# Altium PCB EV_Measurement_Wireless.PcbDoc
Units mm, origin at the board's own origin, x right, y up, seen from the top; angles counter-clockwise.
Board outline 60 x 45 mm, 4 copper layers (Top Layer, Mid-Layer 1, Mid_Layer 2, Bottom Layer), stack 0.605 mm thick; 30 components, 26 nets, 281 pads, 0 vias.
Unrouted connection lines stored in the file: 178.
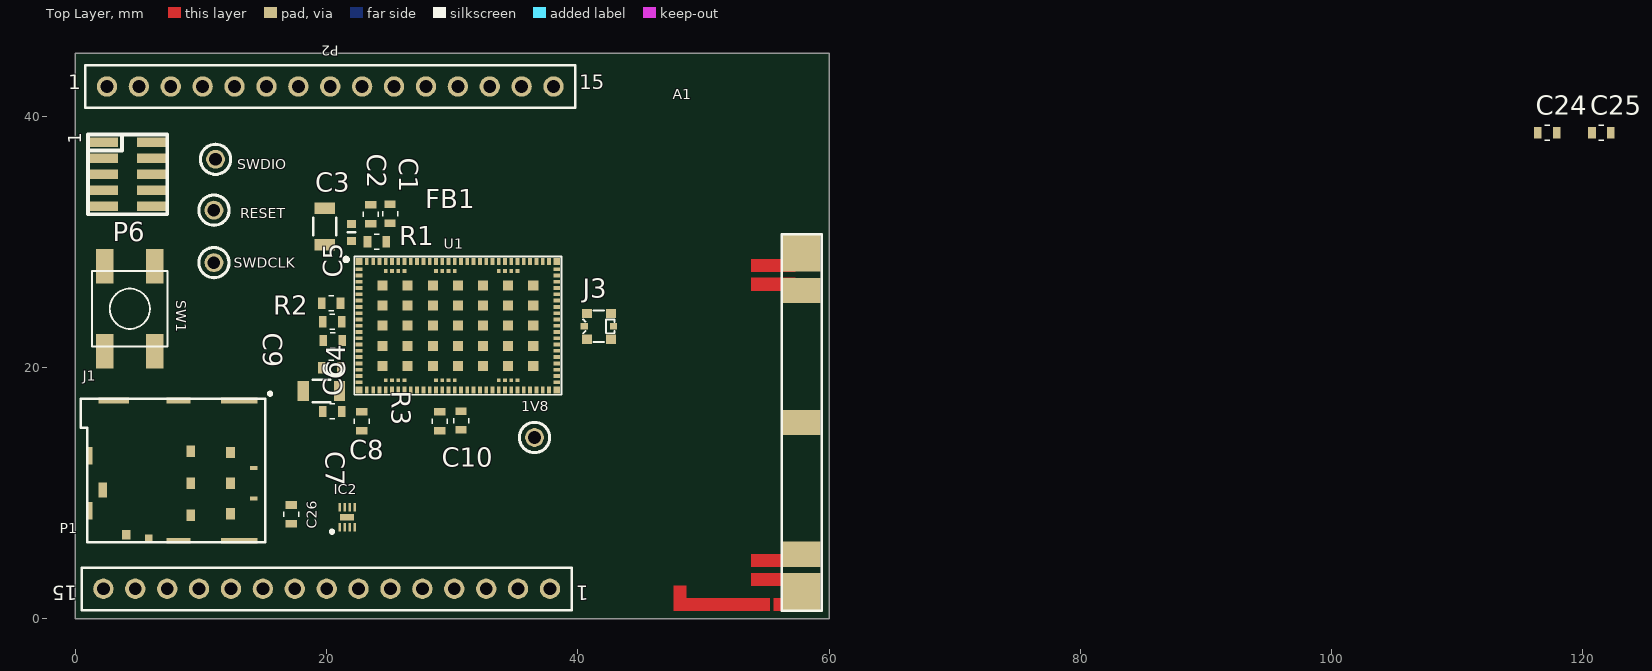
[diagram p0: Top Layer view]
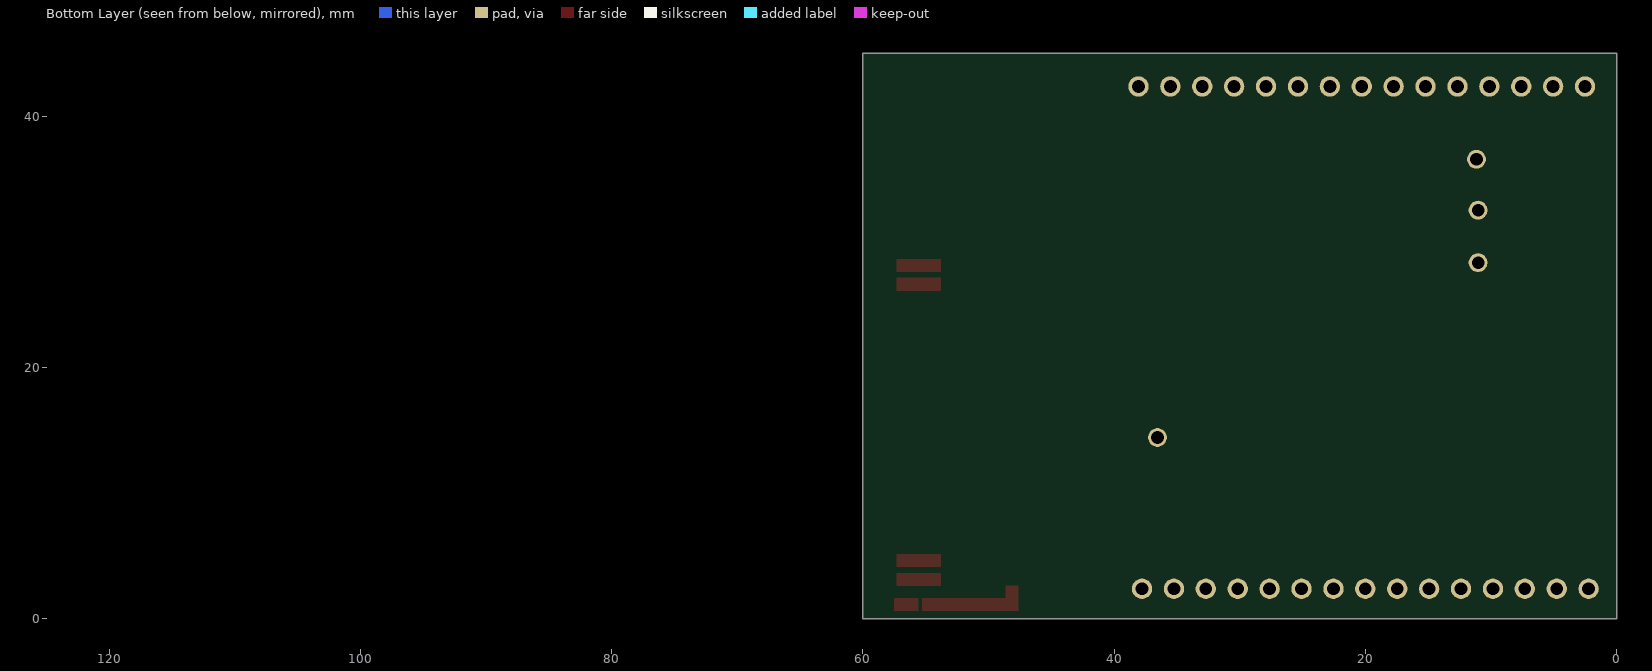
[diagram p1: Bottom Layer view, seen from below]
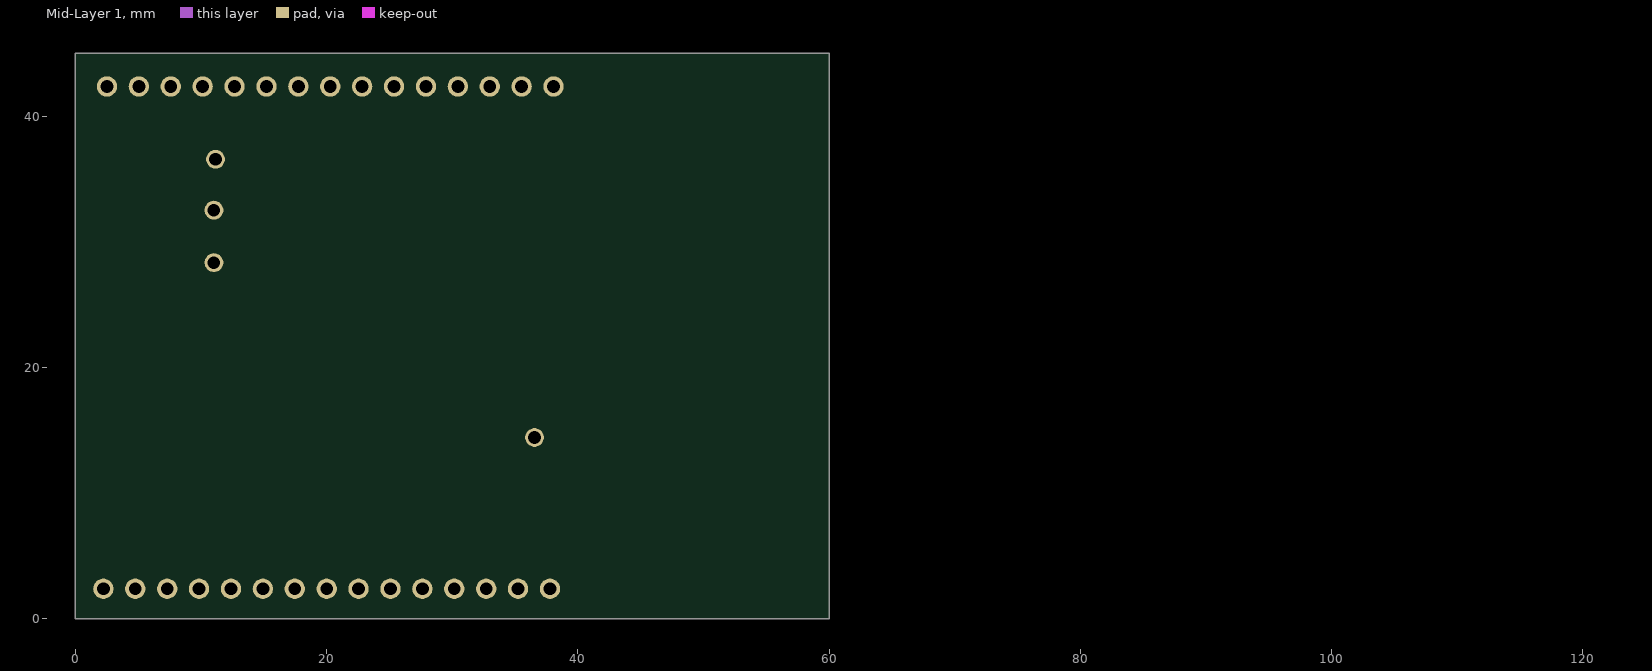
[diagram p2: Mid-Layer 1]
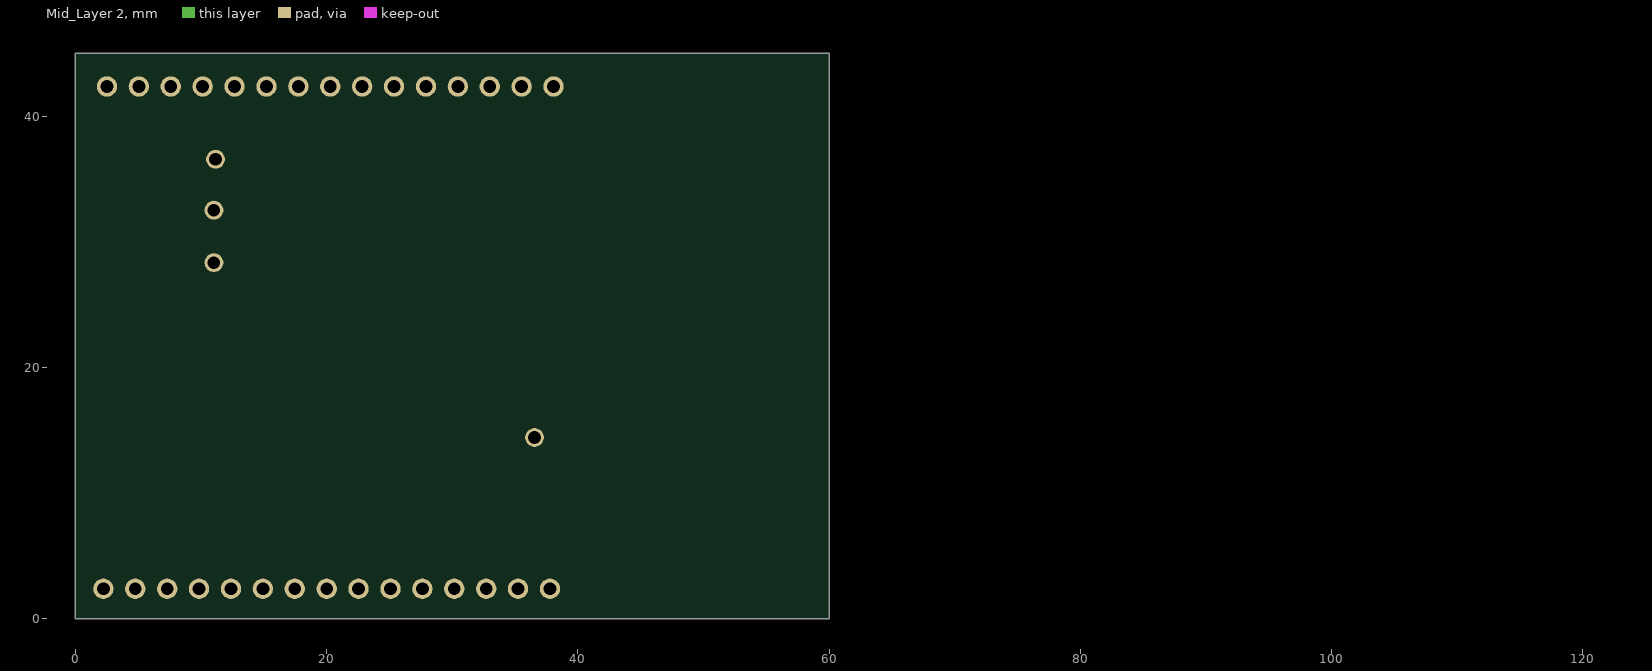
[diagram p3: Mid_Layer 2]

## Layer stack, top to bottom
Top Solder: solder mask 0.0102, Solder Resist, Dk 3.5
Top Layer: signal copper 0.0356
Dielectric 2: prepreg 0.0711, PP-006, Dk 4.1
Mid-Layer 1: signal copper 0.0356
Dielectric 1: prepreg 0.0711, PP-006, Dk 4.1
Mid_Layer 2: signal copper 0.0356
Dielectric2: dielectric 0.32, FR-4, Dk 4.1
Bottom Layer: signal copper 0.0356
Bottom Solder: solder mask 0.0102, Solder Resist, Dk 3.5

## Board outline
0,0 0,45 60,45 60,0

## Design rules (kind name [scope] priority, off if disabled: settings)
Clearance [All] p1: gap=0.254 ignorepadtopadclearanceinfootprint=FALSE
PolygonConnect [All] p1: connectstyle=Relief reliefconductorwidth=0.254 reliefentries=4 polygonreliefangle="90 Angle" airgapwidth=0.254
RoutingVias [All] p1: holewidth=0.711 width=1.27 viastyle="Through Hole" minholewidth=0.711 minwidth=1.27 maxholewidth=0.711 maxwidth=1.27
SolderMaskExpansion [All] p1: expansion=0.102 istentingtop=FALSE
SupplyNets "Schematic Supply Nets" [InNet('VDD_GPIO')] p1: voltage=0.000
SupplyNets "Schematic Supply Nets_1" [InNet('GND')] p2: voltage=0.000
Width [All] p1: maxlimit=0.254 minlimit=0.254 preferedwidth=0.254
30 further rules are at their usual default settings.

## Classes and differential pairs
component class sheet4_sim_connections: 1V8 C24 C25 C26 IC2 J1 P1 P2 P6 RESET SWDCLK SWDIO
component class sheet2_nRF9160: A1 C1 C2 C3 C4 C5 C6 C7 C8 C9 C10 FB1 J3 R1 R2 R3 SW1 U1

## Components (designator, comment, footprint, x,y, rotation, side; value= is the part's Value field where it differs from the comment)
1V8 "TESTPOINT_Black_Small" Testpoint_Black_Small 36.55,14.425 r0 top
A1 "FR01-S4-210" FR01-S4-210_DF 57.825,15.625 r270 top
C1 "39p" 0603(1608)C 25.05,32.25 r90 top
C2 "100n" 0603(1608)C 23.5,32.2 r90 top
C3 "47u" 1206(3216)C 19.85,31.225 r270 top
C4 "100n" 0603(1608)C 20.45,23.65 r180 top
C5 "4u7" 0603(1608)C 20.35,25.125 r180 top
C6 "4u7" 0603(1608)C 20.475,22.15 r180 top
C7 "15p" 0603(1608)C 20.45,16.5 r180 top value=39p
C8 "100n" 0603(1608)C 22.8,15.725 r270 top
C9 "47u" 1206(3216)C 19.575,18.125 r180 top
C10 "100n" 0603(1608)C 30.7,15.775 r90 top
C24 "100n" 0603(1608)C 117.184,38.692 r0 top
C25 "100n" 0603(1608)C 121.502,38.692 r0 top
C26 "100n" 0603(1608)C 17.175,8.3 r270 top
FB1 "BLM18EG221SN1D" BLM18SP221SN1B 21.975,30.75 r270 top
IC2 "EMIF03SIM02M8" SON40P150X170X60-9N-D 21.625,8.075 r90 top
J1 "SF72S006VBAR2500" SF72S006VBAR2500 14.945,17.365 r90 top
J3 "MM8130-2600" COAXIAL-SWF 41.675,23.275 r90 top
P1 "SAMTEC-HTSW-115-17-X-SJ" SAMTEC-HTSW-115-17-X-S 20,2.375 r180 top
P2 "SAMTEC-HTSW-115-17-X-SJ" SAMTEC-HTSW-115-17-X-S 20.285,42.375 r0 top
P6 "Pin Header 2x5, 1.27mm" HDR_2x5-SMD-1.27mm-K 4.15,35.375 r270 top
R1 "10k" 0603(1608) 24,30 r0 top
R2 "0" 0603(1608) 20.375,19.975 r0 top value=0E
R3 "1k" 0603(1608) 29,15.725 r270 top
RESET "TESTPOINT_Black_Small" Testpoint_Black_Small 11.025,32.525 r0 top
SW1 "PB SW" Switch-PB-6.2x6.3mm-SMD 4.325,24.675 r90 top
SWDCLK "TESTPOINT_Black_Small" Testpoint_Black_Small 11.025,28.35 r90 top
SWDIO "TESTPOINT_Black_Small" Testpoint_Black_Small 11.15,36.575 r90 top
U1 "nRF9160-SICAB1A" LGA50P1600X1050X104-161N 30.45,23.325 r0 top

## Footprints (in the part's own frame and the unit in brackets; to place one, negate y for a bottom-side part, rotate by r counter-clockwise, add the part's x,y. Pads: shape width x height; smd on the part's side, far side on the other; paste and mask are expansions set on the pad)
0603(1608) [mm] "Chip 0603 (1608 metric)"
  rect 0.6x0.9 smd: 1(-0.75,0) 2(0.75,0)
  silkscreen extent -0.2,-0.6 0.2,0.6, body extent -0.8,-0.4 0.8,0.4, height 0.3
0603(1608)C [mm] "Chip 0603 (1608 metric)"
  rect 0.6x0.9 smd: 1(-0.75,0) 2(0.75,0)
  silkscreen extent -0.2,-0.6 0.2,0.6, body extent -0.8,-0.38 0.8,0.42, height 0.5
1206(3216)C [mm] "Chip Capa 1206 (3216 metric)"
  rect 0.9x1.6 smd: 1(-1.45,0) 2(1.45,0)
  silkscreen extent -0.7,-0.9 0.7,0.9, body extent -1.6,-0.8 1.6,0.8, height 1
BLM18SP221SN1B [mm]
  rect 0.65x0.7 smd: 1(-0.675,0) 2(0.675,0)
  silkscreen extent 0,-0.3 0,0.3, body extent -0.8,-0.4 0.8,0.4, height 0.8
COAXIAL-SWF [mm]
  rect 0.5x0.58 smd: 1(0,1.16) 3(0,-1.16)
  rect 0.75x0.8 smd: 2(-1.025,-0.95) 2(-1.025,0.95) 2(1.025,-0.95) 2(1.025,0.95)
  Top Layer pour cut-out: -0.65,0.55 0.65,0.55 0.65,1.35 -0.65,1.35
  Top Layer pour cut-out: 0.65,-0.55 -0.65,-0.55 -0.65,-1.35 0.65,-1.35
  silkscreen extent -1.25,-1.25 1.25,1.25, body extent -1.26,-1.3 1.26,1.3, height 1.55
FR01-S4-210_DF [mm]
  rect 2x3 smd: 0(0,0) 2(10.5,0) 4(-10.5,0)
  rect 3x3 smd: 1(13.5,0) 3(-13.5,0)
  Top Layer region: 15,-2.243 15,-0.312 14,-0.312 14,-2.243
  Top Layer region: 14,-2.547 15,-2.547 15,-10.022 14,-10.022
  Top Layer region: 13,-0.5 12,-0.5 12,-4 13,-4
  Top Layer region: 11.5,-0.5 10.5,-0.5 10.5,-4 11.5,-4
  Top Layer region: -12,-0.5 -13,-0.5 -13,-4 -12,-4
  Top Layer region: -10.5,-0.5 -11.5,-0.5 -11.5,-4 -10.5,-4
  Top Layer pour cut-out: -25,2 15.4,2 15.4,-10.5 -25,-10.5
  Top Layer region: 15,-9.2 15,-10.2 13,-10.2 13,-9.2
  Mid-Layer 1 pour cut-out: -25,2 15.4,2 15.4,-10.5 -25,-10.5
  Mid_Layer 2 pour cut-out: -25,2 15.4,2 15.4,-10.5 -25,-10.5
  Bottom Layer pour cut-out: -25,2 15.4,2 15.4,-10.5 -25,-10.5
  silkscreen extent -15,-1.6 15,1.6, body extent -15,-1.5 15,1.5, height 1
HDR_2x5-SMD-1.27mm-K [mm]
  rect 0.76x2.4 smd: 1(-2.54,-1.95) 2(-2.54,1.95) 3(-1.27,-1.95) 4(-1.27,1.95) 5(0,-1.95) 6(0,1.95) 7(1.27,-1.95) 8(1.27,1.95) 9(2.54,-1.95) 10(2.54,1.95)
  silkscreen extent -3.18,-3.15 3.18,3.15, body extent -3.14,-2.92 3.14,2.92, height 6.11
LGA50P1600X1050X104-161N [mm]
  rect 0.54x0.54 smd mask+0.05: 1(-7.87,5.12) 21(-7.87,-5.12) 52(7.87,-5.12) 72(7.87,5.12)
  rect 0.54x0.3 smd mask+0.05: 2(-7.87,4.5) 3(-7.87,4) 4(-7.87,3.5) 5(-7.87,3) 6(-7.87,2.5) 7(-7.87,2) 8(-7.87,1.5) 9(-7.87,1) 10(-7.87,0.5) 11(-7.87,0) 12(-7.87,-0.5) 13(-7.87,-1) 14(-7.87,-1.5) 15(-7.87,-2) 16(-7.87,-2.5) 17(-7.87,-3) 18(-7.87,-3.5) 19(-7.87,-4) 20(-7.87,-4.5) 53(7.87,-4.5) 54(7.87,-4) 55(7.87,-3.5) 56(7.87,-3) 57(7.87,-2.5) 58(7.87,-2) 59(7.87,-1.5) 60(7.87,-1) 61(7.87,-0.5) 62(7.87,0) 63(7.87,0.5) 64(7.87,1) 65(7.87,1.5) 66(7.87,2) 67(7.87,2.5) 68(7.87,3) 69(7.87,3.5) 70(7.87,4) 71(7.87,4.5)
  rect 0.3x0.54 smd mask+0.05: 22(-7.25,-5.12) 23(-6.75,-5.12) 24(-6.25,-5.12) 25(-5.75,-5.12) 26(-5.25,-5.12) 27(-4.75,-5.12) 28(-4.25,-5.12) 29(-3.75,-5.12) 30(-3.25,-5.12) 31(-2.75,-5.12) 32(-2.25,-5.12) 33(-1.75,-5.12) 34(-1.25,-5.12) 35(-0.75,-5.12) 36(-0.25,-5.12) 37(0.25,-5.12) 38(0.75,-5.12) 39(1.25,-5.12) 40(1.75,-5.12) 41(2.25,-5.12) 42(2.75,-5.12) 43(3.25,-5.12) 44(3.75,-5.12) 45(4.25,-5.12) 46(4.75,-5.12) 47(5.25,-5.12) 48(5.75,-5.12) 49(6.25,-5.12) 50(6.75,-5.12) 51(7.25,-5.12) 73(7.25,5.12) 74(6.75,5.12) 75(6.25,5.12) 76(5.75,5.12) 77(5.25,5.12) 78(4.75,5.12) 79(4.25,5.12) 80(3.75,5.12) 81(3.25,5.12) 82(2.75,5.12) 83(2.25,5.12) 84(1.75,5.12) 85(1.25,5.12) 86(0.75,5.12) 87(0.25,5.12) 88(-0.25,5.12) 89(-0.75,5.12) 90(-1.25,5.12) 91(-1.75,5.12) 92(-2.25,5.12) 93(-2.75,5.12) 94(-3.25,5.12) 95(-3.75,5.12) 96(-4.25,5.12) 97(-4.75,5.12) 98(-5.25,5.12) 99(-5.75,5.12) 100(-6.25,5.12) 101(-6.75,5.12) 102(-7.25,5.12)
  rect 0.8x0.8 smd mask+0.05: 103(-6,-3.2) 103(-6,-1.6) 103(-6,0) 103(-6,1.6) 103(-6,3.2) 103(-4,-3.2) 103(-4,-1.6) 103(-4,0) 103(-4,1.6) 103(-4,3.2) 103(-2,-3.2) 103(-2,-1.6) 103(-2,0) 103(-2,1.6) 103(-2,3.2) 103(0,-3.2) 103(0,-1.6) 103(0,0) 103(0,1.6) 103(0,3.2) 103(2,-3.2) 103(2,-1.6) 103(2,0) 103(2,1.6) 103(2,3.2) 103(4,-3.2) 103(4,-1.6) 103(4,0) 103(4,1.6) 103(4,3.2) 103(6,-3.2) 103(6,-1.6) 103(6,0) 103(6,1.6) 103(6,3.2)
  rect 0.3x0.3 smd mask+0.05: 104(-5.75,-4.35) 105(-5.25,-4.35) 106(-4.75,-4.35) 107(-4.25,-4.35) 108(-1.75,-4.35) 109(-1.25,-4.35) 110(-0.75,-4.35) 111(-0.25,-4.35) 112(3.25,-4.35) 113(3.75,-4.35) 114(4.25,-4.35) 115(4.75,-4.35) 116(4.75,4.35) 117(4.25,4.35) 118(3.75,4.35) 119(3.25,4.35) 120(-0.25,4.35) 121(-0.75,4.35) 122(-1.25,4.35) 123(-1.75,4.35) 124(-4.25,4.35) 125(-4.75,4.35) 126(-5.25,4.35) 127(-5.75,4.35)
  Top Layer pour cut-out: -8.15,5.4 8.15,5.4 8.15,-5.4 -8.15,-5.4
  silkscreen extent -9.05,-5.5 8.25,5.5, body extent -8.05,-5.3 8.05,5.3, height 1.2
SAMTEC-HTSW-115-17-X-S [mm]
  round 1.62 hole 1.02: 1(-17.78,0) 2(-15.24,0) 3(-12.7,0) 4(-10.16,0) 5(-7.62,0) 6(-5.08,0) 7(-2.54,0) 8(0,0) 9(2.54,0) 10(5.08,0) 11(7.62,0) 12(10.16,0) 13(12.7,0) 14(15.24,0) 15(17.78,0)
  silkscreen extent -19.5,-1.69 19.5,1.69
SF72S006VBAR2500 [mm]
  rect 0.45x2.9 smd: 0(-11.175,1.9) 0(0,1.9)
  rect 0.45x1.9 smd: 0(-11.175,6.75) 0(0,6.75)
  rect 0.75x0.7 smd: 0(-10.675,10.9)
  rect 1.4x0.5 smd: 0(-8.78,13.85) 0(-4.38,13.85)
  rect 0.3x0.6 smd: 0(-7.8,0.75) 0(-5.36,0.75)
  rect 0.45x2.4 smd: 0(0,11.9)
  rect 0.9x0.7 smd: C1(-4.14,2.6) C2(-6.58,2.6) C3(-9.02,2.6) C5(-4.04,5.77) C6(-6.58,5.77) C7(-9.12,5.77)
  rect 0.6x0.6 smd: CSW(-10.95,9.1)
  rect 1.2x0.65 smd: DSW(-7.13,12.775)
  Top Layer pour cut-out: -10.084,9.5 -3.073,9.5 -3.073,-0.025 -10.084,-0.025
  Top Layer pour cut-out: -8.407,13.106 -3.48,13.106 -3.48,9.855 -8.407,9.855
  silkscreen extent -11.3,-0.67 0.67,14.53, body extent -11.2,0.05 0.02,14.4, height 1.25
SON40P150X170X60-9N-D [mm]
  rect 0.7x0.2 smd: 1(-0.8,0.6) 2(-0.8,0.2) 3(-0.8,-0.2) 4(-0.8,-0.6) 5(0.8,-0.6) 6(0.8,-0.2) 7(0.8,0.2) 8(0.8,0.6)
  rect 0.5x1.1 smd: 9(0,0)
  silkscreen extent -1.27,1.07 -1.03,1.32, body extent -0.8,-0.85 0.8,0.85, height 0.6
Switch-PB-6.2x6.3mm-SMD [mm]
  rect 2.75x1.4 smd: 1(-3.375,2) 1(3.375,2) 2(-3.375,-2) 2(3.375,-2)
  silkscreen extent -3,-3 3,3, body extent -4,-3 4,3.3, height 3.1
Testpoint_Black_Small [mm]
  round 1.5 hole 1: 1(0,0)
  silkscreen extent -1.2,-1.2 1.2,1.2, body extent -1.27,-1.27 1.27,1.27, height 4.89

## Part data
1V8 RESET SWDCLK SWDIO: "PCB Test Point, Black, Through Hole Mount, 3.2 mm, Phosphor Bronze", Manufacturer=MULTICOMP, Manufacturer P/N=TEST-1(R)
A1: library part FR01-S4-210-D, "Mobile IoT LTE Multi-Band Antenna", Manufacturer="Fractus Antennas", Part number IPS=80000001819, Supplier Part Number 1=N.A.
C1 C7: library part C0603_1_39p_50V, "Cer Chip Capacitor / 15p/ +-1%/ 50V", Manufacturer=Murata, Manufacturer P/N=GCM1885C1H390FA16J, Special Value 1=+-1%, Special Value 2=50V
C2 C4 C8 C10 C24 C25 C26: library part C0603_5_100n_25V, "Cer Chip Capacitor / 100n/ +-5%/ 25V", Capacitance=100nF, Case Code (Imperial)=0603, Case Code (Metric)=1608, Dielectric=X7R, Manufacturer 1=Yageo, Manufacturer Part Number=CC0603KRX7R8BB104, Max Operating Temperature=125°C, Min Operating Temperature=-55°C, Package Quantity=1, Special Value 1=+-5%, Special Value 2=25V, Supplier Part Number 1=311-1341-1-ND, Tolerance=10%
C3 C9: library part C1206_7_47u_6.3V, "Cer Chip Capacitor / 47u/ +-10%/ 6.3V", Capacitance=47uF, Case Code (Imperial)=1206, Case Code (Metric)=3216, Dielectric=X5R, Manufacturer 1=Samsung, Manufacturer Part Number=CL31A476MQHNNNE, Max Operating Temperature=85°C, Min Operating Temperature=-55°C, Package Quantity=1, Special Value 1=+-20%, Special Value 2=6.3V, Supplier Part Number 1=1276-1167-1-ND, Tolerance=20%
C5 C6: library part C0603_6_4u7_25V, "Cer Chip Capacitor / 4u7/ +-10%/ 25V", Capacitance=4.7uF, Case Code (Imperial)=0603, Case Code (Metric)=1608, Dielectric=X5R, Manufacturer 1=Samsung, Manufacturer Part Number=CL10A475MA8NQNC, Max Operating Temperature=85°C, Min Operating Temperature=-55°C, Package Quantity=1, Special Value 1=+-10%, Special Value 2=25V, Supplier Part Number 1=1276-1903-1-ND, Tolerance=20%
FB1: "Ferrite Bead", Manufacturer_Name="Murata Electronics", Mouser Part Number=81-BLM18EG221SN1D
IC2: "Integrated Circuit", Manufacturer_Name=STMicroelectronics
J1: "n 8 (6 + 2) Position Card Connector NANO SIM Surface Mount, Right Angle Gold", Manufacturer="JAE Electronics", Part number IPS=00000009956, Part number Norautron=N.A., Supplier Part Number 1=670-2799-1-ND
J3: "Coaxial Connector with Switch", Manufacturer=Murata, Part number IPS=00000009955, Part number Norautron=N.A., Supplier Part Number 1=490-4981-1-ND
P6: library part "Pin Header 2x5 SMD, 1.27mm, KS", "Pin Header 2x5, 1.27mm (50mil), SMD, Keying Shroud", Manufacturer=W-CON, Manufacturer Part Number=3132-10MS0BK00R1, Part number IPS=00000009968, Part number Norautron=N.A.
R1: library part R0603_4_10k, "Chip Resistor / 10k/ 1% / 50V / 100mW / 0603(1608)", Case Code (Imperial)=0603, Case Code (Metric)=1608, Manufacturer 1=Susumu, Manufacturer Part Number=RR0816P-103-D, Max Operating Temperature=125°C, Max Power Dissipation=63mW, Min Operating Temperature=-55°C, Package Quantity=1, Resistance=10kR, Special Value 1=1%, Special Value 2=50V, Special Value 3=100mW, Supplier Part Number 1=RR08P10.0KDCT-ND, Temperature Coefficient=25ppm/°C, Tolerance=0.5%, Voltage Rating=75V
R2: library part R0603_0_0E, "Chip Resistor / 0E / 1% / 50V / 100mW / 0603(1608)", Case Code (Imperial)=0603, Case Code (Metric)=1608, Manufacturer 1=Panasonic, Manufacturer Part Number=ERJ-3GEY0R00V, Max Operating Temperature=155°C, Max Power Dissipation=100mW, Min Operating Temperature=-55°C, Package Quantity=1, Resistance=0mR, Special Value 1=1%, Special Value 2=50V, Supplier Part Number 1=311-0.0HRCT-ND, Temperature Coefficient=600ppm/°C, Tolerance=0%, Voltage Rating=75V
R3: library part R0603_3_1k, "Chip Resistor / 1k/ 1% / 50V / 100mW / 0603(1608)", Case Code (Imperial)=1206, Case Code (Metric)=3216, Manufacturer=Panasonic, Manufacturer Part Number=ERA-8AEB102V, Max Operating Temperature=155°C, Max Power Dissipation=250mW, Min Operating Temperature=-55°C, Package Quantity=5000, Resistance=1kR, Special Value 1=1%, Special Value 2=50V, Special Value 3=100mW, Supplier Part Number 1=P1.0KDBCT-ND, Temperature Coefficient=25ppm/°C, Tolerance=0.1%, Voltage Rating=150V
SW1: library part Switch-PB-6.2x6.3mm-SMD, "Tactile Switch, SPNO, SMD, 160gf, 6.2x6.3x2.5mm", Manufacturer=Dailywell, Manufacturer Part Number=TS604VM1-025BR-R, Part number IPS=00000007812, Part number Norautron=N.A.
U1: "Low power System-in-Package with integrated LTE-M/NB-IoT modem and GPS", Manufacturer="Nordic Semiconductor", Part number IPS=80000002329, Part number Norautron=N.A.

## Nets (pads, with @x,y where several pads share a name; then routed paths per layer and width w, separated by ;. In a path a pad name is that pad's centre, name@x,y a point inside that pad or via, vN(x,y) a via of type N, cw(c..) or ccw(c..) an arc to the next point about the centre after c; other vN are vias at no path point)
AIN0: P1.2 U1.23
AIN1: P1.3 U1.24
AIN2: P1.4 U1.25
AIN3: P1.5 U1.26
AIN4: P1.6 U1.28
AIN5: P1.7 U1.29
CLK_SIMEXT: IC2.6 J1.C3
DEC0: C6.1 U1.13
GND: C1.2 C2.2 C3.2 C4.2 C5.2 C6.2 C7.2 C8.2 C9.2 C10.2 C24.2 C25.1 C26.1 IC2.9 J1.0 J1.C5 J3.2 P1.8 P1.9 P1.10 P1.11 P1.12 P1.13 P1.14 P1.15 P2.1 P2.2 P2.3 P2.4 P2.5 P2.6 P2.7 P2.8 P2.9 P2.10 P2.11 P2.12 P2.13 P2.14 P2.15 P6.3 P6.5 P6.9 SW1.1 U1.1 U1.5 U1.6 U1.7 U1.8 U1.9 U1.11 U1.14 U1.17 U1.21 U1.27 U1.31 U1.36 U1.41 U1.44 U1.47 U1.50 U1.52 U1.56 U1.60 U1.62 U1.63 U1.65 U1.66 U1.68 U1.69 U1.72 U1.74 U1.75 U1.76 U1.77 U1.78 U1.79 U1.80 U1.81 U1.82 U1.85 U1.90 U1.94 U1.98 U1.103
GPS_EN: U1.93
GPS_RF1: U1.67
IO_SIMEXT: IC2.5 J1.C7
LTE_RF1: J3.1 U1.61
NetC7_1: C7.1 C8.1 C9.1 R2.2 U1.22
NetC10_1: C10.1 R3.2 U1.32
NetFB1_2: FB1.2 R1.1 U1.102
NetR1_2: R1.2 U1.101
RESET: P6.10 R3.1 RESET.1 SW1.2
RST_SIMEXT: IC2.7 J1.C2
SIM_1V8: 1V8.1 C26.2 IC2.1 IC2.8 J1.C1 U1.49
SIM_CLK: IC2.3 U1.46
SIM_IO: IC2.4 U1.48
SIM_RST: IC2.2 U1.43
SWDCLK: P6.4 SWDCLK.1 U1.33
SWDIO: P6.2 SWDIO.1 U1.34
VDD_GPIO: C1.1 C2.1 C3.1 C4.1 C5.1 C24.1 C25.2 FB1.1 P1.1 P6.1 R2.1 U1.12
pads on no net: A1.0 A1.1 A1.2 A1.3 A1.4 J1.C6 J1.CSW J1.DSW J3.3 P6.6 P6.7 P6.8 U1.2 U1.3 U1.4 U1.10 U1.15 U1.16 U1.18 U1.19 U1.20 U1.30 U1.35 U1.37 U1.38 U1.39 U1.40 U1.42 U1.45 U1.51 U1.53 U1.54 U1.55 U1.57 U1.58 U1.59 U1.64 U1.70 U1.71 U1.73 U1.83 U1.84 U1.86 U1.87 U1.88 U1.89 U1.91 U1.92 U1.95 U1.96 U1.97 U1.99 U1.100 U1.104 U1.105 U1.106 U1.107 U1.108 U1.109 U1.110 U1.111 U1.112 U1.113 U1.114 U1.115 U1.116 U1.117 U1.118 U1.119 U1.120 U1.121 U1.122 U1.123 U1.124 U1.125 U1.126 U1.127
